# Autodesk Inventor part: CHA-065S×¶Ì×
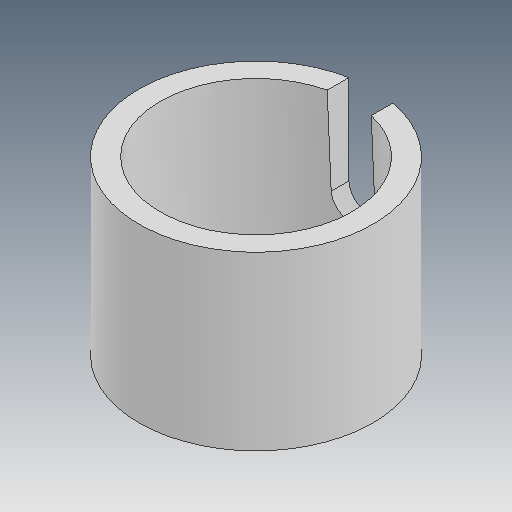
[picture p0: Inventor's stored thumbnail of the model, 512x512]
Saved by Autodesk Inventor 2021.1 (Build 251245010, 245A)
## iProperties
Created: 2019-12
Part Number: CHA-065S×¶Ì×
Material: Ogólny
Document SubType Name: Modeling
Designer: user
Density: 1 g/cm^3
Appearance: Domyślna
Author: user
Revision Number: ÈÎºÎ
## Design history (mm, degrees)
feature "ÊäÈë1"
node "Bryła1"
